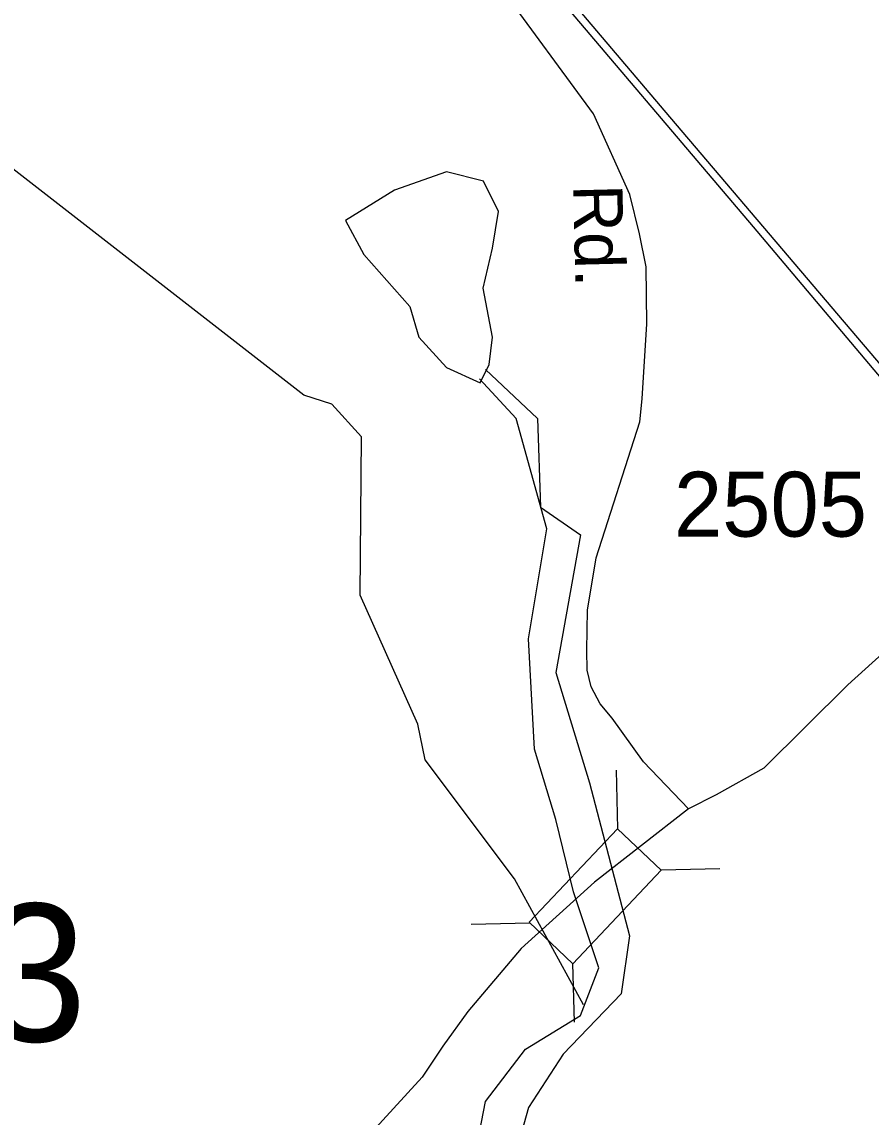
# Model space of a CAD drawing. Extents: x 1364363 to 1407445, y 538563 to 573342.
# Drawn here: x 1379352 to 1380989, y 545755 to 547864 of the extents above; entities that cross this region are included whole.
import ezdxf

# ---------------------------------------------------------------- set-up
doc = ezdxf.new("R2010")
doc.units = 0
for name, color, linetype in [('Exist Civil Demographics City Label', 7, 'Continuous'), ('Exist Hydrographic Creek Double Shore', 7, 'Continuous'), ('Exist Hydrographic Creek Single Shore', 7, 'Continuous'), ('Exist Hydrographic Pond Over 1500 Sq Ft', 7, 'Continuous'), ('Exist Railroad Mainline', 7, 'Continuous'), ('Exist Railroad Siding', 7, 'Continuous'), ('Exist Road Secondary Structure Standard Bridge CELL', 7, 'Continuous'), ('Exist Road Secondary Type 51 Attributed', 7, 'Continuous'), ('Exist Road Secondary Type 51 Label', 7, 'Continuous'), ('Exist Road Secondary Type 51 Number Label', 7, 'Continuous')]:
    doc.layers.add(name, color=color, linetype=linetype)

msp = doc.modelspace()

# ---------------------------------------------------------------- linework, layer by layer
at = {"layer": 'Exist Hydrographic Creek Double Shore'}
for points in [[(1380245.8, 547194.9), (1380346, 547100.5), (1380351.9, 546929.4), (1380428.5, 546876.4), (1380381.4, 546610.9), (1380446.2, 546398.6), (1380522.8, 546103.7), (1380507, 545992.3), (1380395.4, 545875.7), (1380328.3, 545773.3), (1380287.1, 545625.9), (1380292.9, 545466.6), (1380351.9, 545384), (1380463.9, 545336.9), (1380570, 545218.9), (1380617.1, 545059.6), (1380682, 544788.3), (1380782.2, 544599.5), (1380855.6, 544572.8)], [(1380755.6, 544414.1), (1380711.4, 544605.4), (1380658.4, 544782.4), (1380587.7, 544929.9), (1380499.3, 545171.7), (1380369.6, 545319.2), (1380251.7, 545366.3), (1380198.6, 545478.4), (1380210.4, 545602.3), (1380245.8, 545785.1), (1380322.4, 545885.4), (1380428.5, 545950.3), (1380463.7, 546042.3), (1380415.4, 546188.9), (1380381.4, 546327.8), (1380340.1, 546463.5), (1380328.3, 546675.8), (1380363.7, 546888.2), (1380304.7, 547100.5), (1380234, 547177.2)]]:
    msp.add_lwpolyline(points, dxfattribs=at)
at = {"layer": 'Exist Hydrographic Creek Single Shore'}
msp.add_lwpolyline([(1380434.5, 545971.1), (1380301.8, 546214), (1380129.4, 546443.2), (1380115.2, 546511.7), (1380004, 546760), (1380006.8, 547065.3), (1379949.8, 547128.1), (1379895.6, 547145.2), (1379050.8, 547801.7), (1378801.7, 548006)], dxfattribs=at)
at = {"layer": 'Exist Hydrographic Pond Over 1500 Sq Ft'}
msp.add_lwpolyline([(1380252.9, 547204.3), (1380258.8, 547257.4), (1380241.1, 547351.8), (1380258.8, 547428.5), (1380270.6, 547499.3), (1380241.8, 547557.5), (1380170.4, 547575.9), (1380070.2, 547540.5), (1379975.9, 547481.6), (1380011.2, 547416.7), (1380099.6, 547316.4), (1380117.3, 547257.4), (1380170.4, 547198.4), (1380235.2, 547168.9)], close=True, dxfattribs=at)
at = {"layer": 'Exist Railroad Mainline'}
msp.add_lwpolyline([(1381235.1, 546914.3), (1381070.9, 547103.6), (1380761.8, 547470), (1380338.5, 547968.9), (1380018.2, 548346.9), (1379659.7, 548768), (1379519.7, 548935.3)], dxfattribs=at)
at = {"layer": 'Exist Railroad Siding'}
msp.add_lwpolyline([(1379422.2, 549074.9), (1379541.6, 548930.4), (1379683.9, 548762.6), (1379890.1, 548518.7), (1380600.1, 547681.6), (1381225.6, 546946.1)], dxfattribs=at)
at = {"layer": 'Exist Road Secondary Structure Standard Bridge CELL'}
for p, q in [((1380497.2, 546423), (1380500.2, 546309.9)), ((1380697.4, 546233.2), (1380584.2, 546230.2)), ((1380331.2, 546128.5), (1380218, 546125.5)), ((1380413.3, 546050.7), (1380416.3, 545937.5))]:
    msp.add_line(p, q, dxfattribs=at)
msp.add_lwpolyline([(1380584.2, 546230.2), (1380413.7, 546050.3), (1380329.6, 546130), (1380500.2, 546309.9)], close=True, dxfattribs=at)
at = {"layer": 'Exist Road Secondary Type 51 Attributed'}
for points in [[(1380636.6, 546348.8), (1380550.1, 546439.2), (1380489.6, 546523.5), (1380466.4, 546550.7), (1380449.4, 546583.9), (1380441.6, 546615.5), (1380440.7, 546654.4), (1380442.2, 546731.2), (1380458.9, 546831.9), (1380543.1, 547093.8), (1380547.2, 547138.4), (1380556.5, 547282.9), (1380555.3, 547392.7), (1380542.6, 547456.1), (1380523.6, 547532.1), (1380454, 547687.4), (1380274.7, 547932.1), (1380183.1, 548066), (1380139.7, 548123.2)], [(1381354.9, 546957.3), (1381331.4, 546930.2), (1381281.3, 546888), (1381210.4, 546826.4), (1381044, 546677.7), (1380944, 546587.6), (1380782, 546427.2), (1380689.8, 546375.4), (1380636.6, 546348.8)], [(1380636.6, 546348.8), (1380455.7, 546207.6)], [(1380455.7, 546207.6), (1380314.6, 546079.8), (1380211.4, 545958.1), (1380163.5, 545891.6), (1380123.6, 545831.9), (1379992.6, 545688.4)]]:
    msp.add_lwpolyline(points, dxfattribs=at)

# ---------------------------------------------------------------- texts
at = {"layer": 'Exist Civil Demographics City Label'}
msp.add_text('pop. 3,363', height=265, dxfattribs=at).set_placement((1377802.4, 545900.6))
at = {"layer": 'Exist Road Secondary Type 51 Label'}
msp.add_text('Rd.', height=95, rotation=271.4057, dxfattribs=at).set_placement((1380414.3, 547550.4))
at = {"layer": 'Exist Road Secondary Type 51 Number Label'}
msp.add_text('2505', height=125, dxfattribs=at).set_placement((1380608.8, 546872.9))

doc.saveas('drawing.dxf')
